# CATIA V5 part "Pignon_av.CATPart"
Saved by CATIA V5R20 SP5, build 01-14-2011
Part number: Skl_Pignon_av
Publications: "Plan xy", "Axe_pivot_pignon_av/bras_av"
Bounding box of the stored display mesh (mm): x -5 to 5, y 0 to 420, z -10 to 150
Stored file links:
  U:\2A\CFAO\dossier sans titre\Pignon_av.CATPart
  U:\2A\CFAO\dossier sans titre\Skl_gouvernail.CATProduct
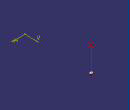
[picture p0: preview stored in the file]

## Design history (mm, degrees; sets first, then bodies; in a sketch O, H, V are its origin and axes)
Set1
  Point1 to Point3: linked copy from another document
Body1 (main body)
  Line1 "Axe_pivot_pignon_av/bras_av": type PtPt, FirstPoint Point1, SecondPoint Point2
  Line2: type PtPt, FirstPoint Point1, SecondPoint Point3
  Sketch1 on xy-plane, origin (0, 0, 0), H (1, 0, 0), V (0, 1, 0)
    circle A1 centre (0, 414.9997) radius 5
    point P1 (0, 414.9997)
    reference projected point E1 (0, 414.9997) from Point2
    reference projected point E2 (0, 409.9997) from Point3
    coincidence: P1 E1, A1 E2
